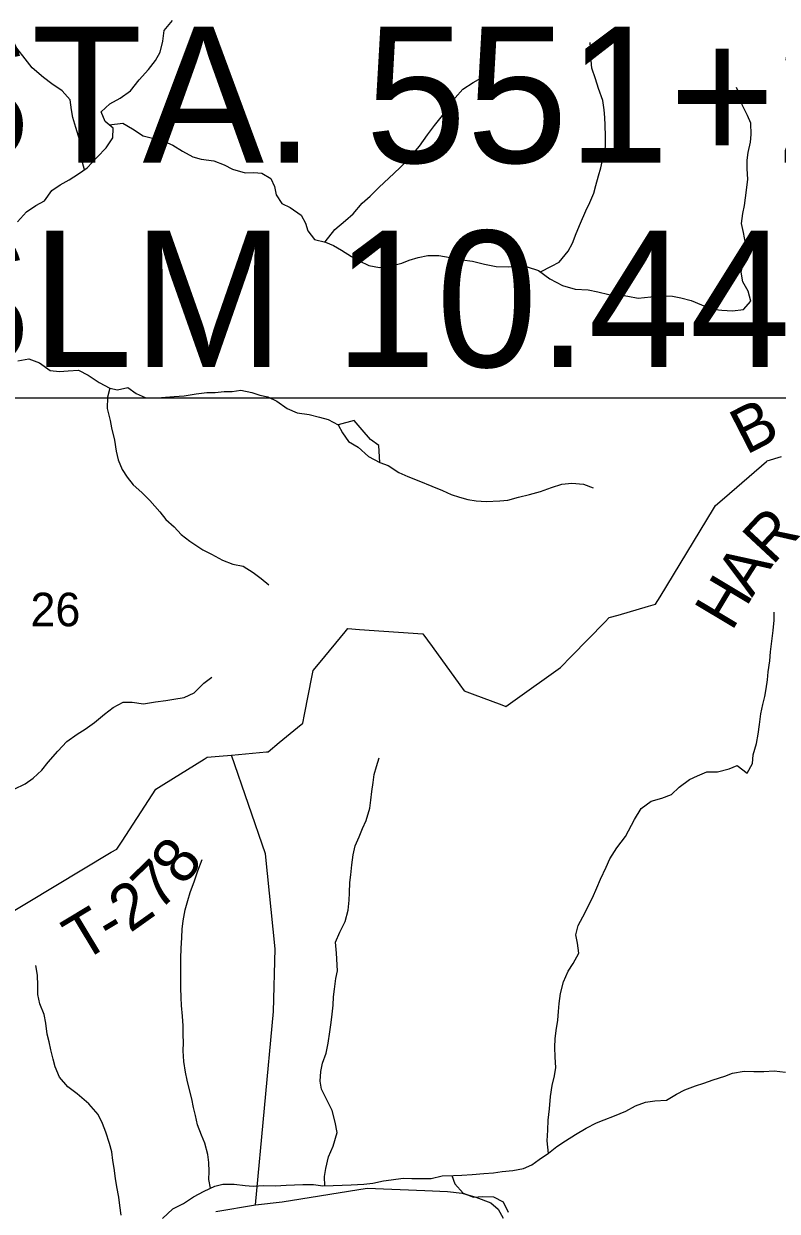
# Model space of a CAD drawing. Extents: x 0 to 34, y 0 to 22.
# Drawn here: x 2.947 to 3.888, y 14.793 to 16.276 of the extents above; entities that cross this region are included whole.
import ezdxf

# ---------------------------------------------------------------- set-up
doc = ezdxf.new("R2010")
doc.units = 0
for name, color, linetype in [('GM_X_County_Road', 7, 'Continuous'), ('GM_X_Minor_Lake', 7, 'Continuous'), ('GM_X_Minor_River', 7, 'Continuous'), ('GM_X_Section_Text', 7, 'Continuous'), ('GM_X_Township_Road', 7, 'Continuous'), ('GM_X_Township_Road_Text', 7, 'Continuous'), ('SH_Text', 7, 'Continuous')]:
    doc.layers.add(name, color=color, linetype=linetype)

msp = doc.modelspace()

# ---------------------------------------------------------------- linework, layer by layer
at = {"layer": 'GM_X_County_Road'}
msp.add_lwpolyline([(3.1871, 14.7929), (3.2367, 14.8014), (3.27, 14.8052), (3.376, 14.8221), (3.448, 14.8193), (3.4764, 14.8179), (3.4945, 14.8157), (3.5116, 14.8111), (3.5304, 14.8037), (3.5393, 14.7958), (3.5457, 14.7845)], dxfattribs=at)
at = {"layer": 'GM_X_Minor_Lake'}
for points in [[(3.3917, 15.728), (3.3906, 15.7492), (3.38, 15.7568), (3.3699, 15.769), (3.3597, 15.7808), (3.3396, 15.7752)], [(3.3396, 15.7752), (3.3453, 15.7653), (3.3528, 15.7543), (3.3649, 15.7474), (3.3777, 15.7356), (3.3917, 15.728)]]:
    msp.add_lwpolyline(points, dxfattribs=at)
at = {"layer": 'GM_X_Minor_River'}
for points in [[(3.023, 16.0936), (3.0182, 16.1118), (3.0194, 16.1247), (3.0156, 16.1357), (3.0123, 16.1464), (3.0085, 16.1589), (3.0071, 16.1684), (3.0052, 16.1809), (2.9954, 16.1923), (2.9822, 16.201), (2.972, 16.2087), (2.9577, 16.2209), (2.949, 16.2323), (2.9385, 16.2456), (2.9313, 16.2562), (2.9219, 16.2699), (2.9125, 16.2843)], [(2.9396, 16.0287), (2.9506, 16.0412), (2.9624, 16.0491), (2.9733, 16.0548), (2.9825, 16.0676), (2.9927, 16.0748), (3.0041, 16.0812), (3.0155, 16.0887), (3.0265, 16.0959), (3.039, 16.1095), (3.05, 16.1212), (3.0584, 16.1337), (3.0588, 16.1454), (3.049, 16.1538), (3.0441, 16.1659), (3.0547, 16.1758), (3.0676, 16.1829), (3.0805, 16.1923), (3.0912, 16.2059), (3.1029, 16.2188), (3.1117, 16.2301), (3.1178, 16.2403), (3.1209, 16.254), (3.1224, 16.2676), (3.1331, 16.2801)], [(3.5923, 15.966), (3.6059, 15.9732), (3.6154, 15.9781), (3.6268, 15.9921), (3.6321, 16.0019), (3.6367, 16.014), (3.6421, 16.0269), (3.6489, 16.0424), (3.6539, 16.0526), (3.6589, 16.0644), (3.6615, 16.0742), (3.6646, 16.0859), (3.6677, 16.0962), (3.6711, 16.1113), (3.6734, 16.1223), (3.6735, 16.1356), (3.6732, 16.1492), (3.6724, 16.1587), (3.6717, 16.1685), (3.6702, 16.1803), (3.6646, 16.1951), (3.6609, 16.2073), (3.6564, 16.2205), (3.6557, 16.23), (3.6553, 16.2399), (3.6542, 16.2524)], [(3.3236, 16.0035), (3.3356, 16.0189), (3.3489, 16.0302), (3.3584, 16.0385), (3.3698, 16.0518), (3.3797, 16.0605), (3.391, 16.0718), (3.4032, 16.0831), (3.4169, 16.0959), (3.429, 16.1084), (3.4412, 16.1232), (3.4511, 16.1371), (3.4602, 16.1489), (3.4682, 16.1594), (3.4788, 16.1727), (3.486, 16.1836), (3.4955, 16.1942), (3.5084, 16.2025), (3.5209, 16.2097)], [(3.0538, 16.1497), (3.0709, 16.1518), (3.083, 16.1446), (3.0962, 16.1362), (3.1098, 16.1327), (3.123, 16.1289), (3.1332, 16.1243), (3.1453, 16.1167), (3.1582, 16.1098), (3.1687, 16.1067), (3.1846, 16.1048), (3.1975, 16.0998), (3.208, 16.0944), (3.2235, 16.0898), (3.2345, 16.0902), (3.2443, 16.0894), (3.2557, 16.0829), (3.2605, 16.0726), (3.2624, 16.0624), (3.2695, 16.0514), (3.2797, 16.0464), (3.2937, 16.0369), (3.299, 16.027), (3.3019, 16.0175), (3.3102, 16.0065), (3.3238, 16.0034), (3.334, 15.9992), (3.3438, 15.9931), (3.3563, 15.9855), (3.3661, 15.9801), (3.3782, 15.974), (3.3914, 15.9717), (3.4039, 15.9732), (3.4191, 15.9769), (3.4285, 15.9807), (3.4395, 15.984), (3.4516, 15.9867), (3.4653, 15.9866), (3.4796, 15.9843), (3.4944, 15.9812), (3.5076, 15.9796), (3.5223, 15.9758), (3.5371, 15.9727), (3.5522, 15.9726), (3.5628, 15.9737), (3.5757, 15.9726), (3.5896, 15.968), (3.604, 15.9573), (3.6198, 15.9493), (3.6357, 15.9447), (3.652, 15.9438), (3.6637, 15.9411), (3.6777, 15.9377), (3.6909, 15.9376), (3.7015, 15.9357), (3.7144, 15.9334), (3.7299, 15.9348), (3.7439, 15.9363), (3.7571, 15.9359), (3.7673, 15.9339), (3.7805, 15.9305), (3.7934, 15.9248), (3.8066, 15.9198), (3.8187, 15.9182), (3.8319, 15.9174), (3.8456, 15.9193), (3.8547, 15.9295), (3.8513, 15.942), (3.8449, 15.9537), (3.8427, 15.9659), (3.8462, 15.9799), (3.8477, 15.9894), (3.8481, 16.0019), (3.8455, 16.0155), (3.8433, 16.0265), (3.8449, 16.039), (3.8468, 16.0489), (3.848, 16.0587), (3.8511, 16.0815), (3.8504, 16.0951), (3.8504, 16.1057), (3.8516, 16.1152), (3.8543, 16.1281), (3.8551, 16.1376), (3.8548, 16.152), (3.8506, 16.1615), (3.8442, 16.1747), (3.8416, 16.1869), (3.8371, 16.1964)], [(2.9401, 15.8551), (2.9537, 15.8577), (2.9669, 15.8524), (2.9801, 15.8429), (2.9918, 15.8417), (3.0028, 15.8428), (3.0157, 15.8435), (3.0278, 15.8374), (3.0414, 15.8282), (3.0546, 15.821), (3.0644, 15.819), (3.0773, 15.822), (3.0878, 15.8144), (3.0988, 15.8094), (3.1139, 15.809), (3.1241, 15.8097), (3.1351, 15.8104), (3.1476, 15.8115), (3.1624, 15.8137), (3.176, 15.8156), (3.1862, 15.8155), (3.1975, 15.8166), (3.2074, 15.817), (3.2184, 15.8185), (3.232, 15.8154), (3.2418, 15.8123), (3.252, 15.81), (3.2633, 15.8046), (3.2762, 15.7955), (3.2886, 15.7902), (3.3034, 15.7882), (3.3166, 15.7847), (3.3272, 15.7817), (3.3396, 15.7752), (3.3453, 15.7653), (3.3528, 15.7543), (3.3649, 15.7474), (3.3777, 15.7356), (3.3917, 15.728), (3.4022, 15.7245), (3.4155, 15.7158), (3.4268, 15.7108), (3.4404, 15.7051), (3.4566, 15.6986), (3.4698, 15.6932), (3.4808, 15.6882), (3.4914, 15.6848), (3.5016, 15.6821), (3.5122, 15.6805), (3.5243, 15.6794), (3.5417, 15.6801), (3.5515, 15.6812), (3.5648, 15.6849), (3.5784, 15.6883), (3.5924, 15.692), (3.606, 15.6969), (3.6189, 15.701), (3.6314, 15.7025), (3.6458, 15.7009), (3.6582, 15.6967)], [(3.0546, 15.821), (3.0519, 15.8096), (3.0514, 15.7956), (3.0552, 15.7808), (3.057, 15.7713), (3.0604, 15.7561), (3.0626, 15.7421), (3.0652, 15.7315), (3.0701, 15.7193), (3.0765, 15.7098), (3.084, 15.7003), (3.0946, 15.6908), (3.1047, 15.6809), (3.1172, 15.6665), (3.1247, 15.657), (3.1349, 15.6478), (3.1439, 15.6383), (3.1545, 15.6299), (3.1707, 15.6193), (3.1817, 15.6139), (3.1953, 15.6063), (3.2081, 15.6013), (3.2213, 15.5986), (3.2338, 15.591), (3.2436, 15.5834), (3.2534, 15.5754)], [(3.6021, 14.8656), (3.6008, 14.8812), (3.6016, 14.8945), (3.602, 14.907), (3.6035, 14.9214), (3.6047, 14.9365), (3.6067, 14.9502), (3.6098, 14.9623), (3.6113, 14.9729), (3.6106, 14.9858), (3.6103, 14.9983), (3.6107, 15.0085), (3.6119, 15.0188), (3.6138, 15.032), (3.6146, 15.0426), (3.6158, 15.0525), (3.6173, 15.0654), (3.6208, 15.0797), (3.6269, 15.093), (3.633, 15.1028), (3.6402, 15.1157), (3.6384, 15.1282), (3.6365, 15.1384), (3.6392, 15.1502), (3.6453, 15.1611), (3.6571, 15.1846), (3.6625, 15.1971), (3.667, 15.2081), (3.6743, 15.2228), (3.6789, 15.2334), (3.6876, 15.247), (3.6982, 15.2614), (3.7097, 15.2826), (3.718, 15.2962), (3.7306, 15.3052), (3.7438, 15.309), (3.7556, 15.3135), (3.7654, 15.3229), (3.7783, 15.3324), (3.7882, 15.3369), (3.7999, 15.3418), (3.8132, 15.3421), (3.8279, 15.3458), (3.8378, 15.35), (3.8502, 15.3401), (3.8571, 15.3525), (3.8579, 15.3631), (3.8617, 15.3772), (3.864, 15.3889), (3.8656, 15.401), (3.8672, 15.4143), (3.8698, 15.426), (3.8722, 15.4359), (3.8741, 15.4457), (3.8756, 15.4567), (3.8764, 15.4669), (3.8784, 15.4806), (3.8795, 15.4916), (3.8811, 15.5052), (3.8827, 15.5185), (3.8839, 15.5313), (3.8839, 15.5412)], [(2.9354, 15.3203), (2.9491, 15.3271), (2.9589, 15.3339), (2.97, 15.3441), (2.9779, 15.3539), (2.9897, 15.3679), (3.0011, 15.38), (3.014, 15.389), (3.0239, 15.3954), (3.0356, 15.4037), (3.0481, 15.4139), (3.0591, 15.4222), (3.0713, 15.429), (3.0826, 15.4289), (3.0966, 15.427), (3.1118, 15.4292), (3.1246, 15.4311), (3.1345, 15.4325), (3.1477, 15.4348), (3.1602, 15.4404), (3.172, 15.4525), (3.1819, 15.46)], [(3.323, 14.8251), (3.3229, 14.8368), (3.3245, 14.8466), (3.3275, 14.8614), (3.3337, 14.8746), (3.3386, 14.8917), (3.336, 14.9046), (3.3323, 14.919), (3.3188, 14.9456), (3.3173, 14.9558), (3.3181, 14.9679), (3.32, 14.9781), (3.3246, 14.9906), (3.3273, 15.0031), (3.3293, 15.0172), (3.3312, 15.0289), (3.3324, 15.0395), (3.3335, 15.0505), (3.334, 15.0611), (3.3351, 15.0706), (3.3367, 15.0838), (3.339, 15.0937), (3.3376, 15.1157), (3.3365, 15.1293), (3.3418, 15.1418), (3.3487, 15.155), (3.3521, 15.1694), (3.3533, 15.1816), (3.3537, 15.191), (3.3545, 15.2039), (3.3557, 15.2134), (3.3569, 15.2259), (3.3585, 15.2384), (3.3611, 15.2494), (3.3661, 15.2607), (3.3703, 15.2713), (3.3749, 15.2812), (3.3791, 15.2967), (3.3806, 15.3065), (3.3818, 15.3175), (3.3834, 15.3285), (3.3849, 15.3387), (3.3876, 15.3486), (3.3911, 15.3596)], [(3.1804, 14.8221), (3.1784, 14.8331), (3.1788, 14.843), (3.1785, 14.8544), (3.177, 14.8642), (3.1733, 14.8783), (3.1691, 14.8885), (3.1643, 14.9014), (3.1617, 14.9128), (3.1591, 14.9227), (3.1572, 14.9337), (3.1538, 14.9466), (3.1512, 14.9568), (3.1494, 14.967), (3.1472, 14.9803), (3.1461, 14.9936), (3.1469, 15.0042), (3.1465, 15.0137), (3.1462, 15.0247), (3.1455, 15.0368), (3.1444, 15.0504), (3.1437, 15.0603), (3.1433, 15.0724), (3.1435, 15.1092), (3.1439, 15.1213), (3.1447, 15.135), (3.1451, 15.1456), (3.1463, 15.1558), (3.149, 15.1698), (3.1521, 15.1812), (3.1551, 15.1914), (3.1605, 15.2058), (3.1647, 15.2183), (3.17, 15.2323)], [(3.0689, 14.7884), (3.0674, 14.8006), (3.066, 14.8108), (3.0637, 14.8237), (3.0619, 14.8343), (3.06, 14.8472), (3.0586, 14.8567), (3.0571, 14.8677), (3.0545, 14.8779), (3.0496, 14.892), (3.0455, 14.903), (3.0402, 14.914), (3.0286, 14.9273), (3.0142, 14.9399), (3.0022, 14.9486), (2.992, 14.9608), (2.9867, 14.9737), (2.9841, 14.9832), (2.9811, 14.995), (2.9789, 15.0048), (2.9767, 15.0143), (2.9748, 15.0283), (2.973, 15.0389), (2.9674, 15.0522), (2.9651, 15.064), (2.9648, 15.075), (2.9645, 15.0879), (2.9622, 15.1)], [(3.7962, 14.9533), (3.808, 14.9574), (3.8224, 14.9619), (3.8318, 14.9656), (3.8466, 14.9682), (3.8587, 14.9678), (3.8712, 14.9678), (3.884, 14.9685), (3.898, 14.9669)], [(3.1207, 14.7841), (3.1336, 14.7962), (3.1469, 14.8029), (3.159, 14.8112), (3.1727, 14.8184), (3.1859, 14.8248), (3.1958, 14.827), (3.2101, 14.827), (3.2238, 14.8254), (3.2336, 14.8246), (3.2468, 14.8253), (3.2616, 14.8252), (3.2748, 14.826), (3.2854, 14.8263), (3.2956, 14.8266), (3.3089, 14.8266), (3.3206, 14.825), (3.3335, 14.8254), (3.3448, 14.8261), (3.3558, 14.8264), (3.3717, 14.8271), (3.383, 14.8282), (3.3963, 14.8312), (3.4061, 14.8327), (3.4209, 14.8345), (3.4319, 14.8341), (3.4417, 14.8341), (3.4557, 14.8344), (3.4697, 14.8374), (3.4837, 14.8381), (3.4943, 14.8384), (3.5072, 14.8391), (3.5215, 14.8406), (3.5336, 14.8413), (3.5446, 14.8431), (3.5579, 14.8442), (3.5711, 14.8465), (3.5813, 14.8513), (3.5908, 14.8578), (3.6022, 14.8657), (3.6128, 14.874), (3.6234, 14.8811), (3.636, 14.889), (3.6492, 14.897), (3.6621, 14.9037), (3.6716, 14.9075), (3.6845, 14.9124), (3.6989, 14.9184), (3.711, 14.9248), (3.7235, 14.9297), (3.7352, 14.9311), (3.7496, 14.9322), (3.7621, 14.9394), (3.7724, 14.945), (3.7856, 14.9499), (3.7962, 14.9533)], [(3.4816, 14.838), (3.4852, 14.8274), (3.4957, 14.8157), (3.5086, 14.8111), (3.5203, 14.8118), (3.5335, 14.8114), (3.5456, 14.8052), (3.552, 14.792)]]:
    msp.add_lwpolyline(points, dxfattribs=at)
at = {"layer": 'GM_X_Township_Road'}
for points in [[(2.9158, 15.1571), (3.0566, 15.2417), (3.0636, 15.2454), (3.0701, 15.2553), (3.1077, 15.3134), (3.1122, 15.3202), (3.122, 15.3264), (3.1724, 15.3577), (3.1763, 15.3601), (3.1914, 15.3615), (3.2068, 15.3629), (3.2505, 15.3668), (3.2522, 15.367), (3.2661, 15.3784), (3.2891, 15.3972), (3.2958, 15.4027), (3.2979, 15.4136), (3.3075, 15.4621), (3.3087, 15.4684), (3.3172, 15.4787), (3.3486, 15.5168), (3.3519, 15.5208), (3.3665, 15.5198), (3.4454, 15.5144), (3.4571, 15.4986), (3.4918, 15.4505), (3.4972, 15.443), (3.507, 15.4393), (3.5441, 15.4255), (3.5492, 15.4236), (3.5608, 15.4319), (3.6171, 15.4722), (3.6309, 15.4863), (3.6725, 15.5287), (3.6782, 15.5345), (3.6893, 15.5377), (3.7273, 15.5488), (3.7358, 15.5512), (3.7415, 15.5605), (3.8082, 15.6704), (3.8106, 15.6743), (3.8221, 15.6842), (3.8745, 15.7293), (3.8754, 15.7301), (3.8931, 15.7358)], [(3.2367, 14.8014), (3.2591, 15.0427), (3.2611, 15.121), (3.249, 15.2396), (3.2068, 15.3629)]]:
    msp.add_lwpolyline(points, dxfattribs=at)
at = {"layer": 'SH_Text'}
msp.add_lwpolyline([(2.7795, 16.5585), (4.7911, 16.5585), (4.7911, 15.8085), (2.7795, 15.8085)], close=True, dxfattribs=at)

# ---------------------------------------------------------------- texts
at = {"layer": 'GM_X_Section_Text'}
msp.add_text('26', height=0.04186, rotation=0, dxfattribs=at).set_placement((2.9557, 15.5237))
at = {"layer": 'GM_X_Township_Road_Text'}
for s, rotation, p in [('B', 27.1079, (3.8488, 15.7372)), ('R', 47.0565, (3.8816, 15.5988)), ('A', 57.3617, (3.8563, 15.5589)), ('H', 59.0925, (3.8309, 15.5163)), ('8', 52.8019, (3.147, 15.1979)), ('7', 44.1201, (3.1157, 15.1665)), ('2', 35.4384, (3.08, 15.1402)), ('T', 31.0975, (3.0197, 15.1036)), ('-', 31.0975, (3.0561, 15.1255))]:
    msp.add_text(s, height=0.0568, rotation=rotation, dxfattribs=at).set_placement(p)
at = {"layer": 'SH_Text'}
for s, p in [('STA. 551+25.00', (2.8051, 16.1024)), ('SLM 10.44', (2.8051, 15.8474))]:
    msp.add_text(s, height=0.17, dxfattribs=at).set_placement(p)

doc.saveas('drawing.dxf')
